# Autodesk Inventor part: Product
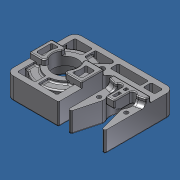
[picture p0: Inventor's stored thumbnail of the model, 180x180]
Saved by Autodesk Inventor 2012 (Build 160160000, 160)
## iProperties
Created: 2018-02
Part Number: Product
Material: Default
Document SubType Name: Modeling
Designer: Admin
Density: 1 g/cm^3
Author: Admin
Translation Standard: STEP AP203
FileName: 22-1190-0.stp
PreProcessor: Mechanical Desktop 2011
PostProcessor: Build: 160, Release: 2012 RTM - Date: Tue 03/01/2011
Sent Units: inch
Uncertainty: 1.0000000000000002e-06
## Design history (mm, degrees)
feature "Base3"
node "307"
node "301"
